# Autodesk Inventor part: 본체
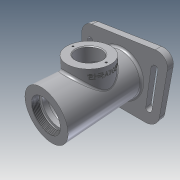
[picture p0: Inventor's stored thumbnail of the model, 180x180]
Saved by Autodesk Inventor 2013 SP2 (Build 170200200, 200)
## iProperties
Created: 2021-07
Part Number: 본체
Material: 알루미늄 6061
Document SubType Name: Modeling
Designer: kumcom17
Density: 2.71 g/cm^3
Mass: 738.12 g
Surface Area: 645.231 cm^2
Volume: 272.369 cm^3
Author: kumcom17
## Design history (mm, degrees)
sketch "스케치1"
  geometry: L1 (-56, 0)-(59, 0); L2 (59, 0)-(59, 31); L3 (59, 31)-(-56, 31); L4 (-56, 31)-(-56, 0); L5 (-56, 21)-(-47, 21); L6 (-47, 21)-(-47, 24); L7 (-47, 24)-(-44, 24); L8 (-44, 24)-(-44, 20); L9 (-44, 20)-(-37.5, 20); L10 (-35, 17.5)-(-35, 17.5); L11 (-35, 17.5)-(-31.75, 17.5); L12 (-31.75, 17.5)-(-31.75, 18.5); L13 (-31.75, 18.5)-(-30, 18.5); L14 (-30, 18.5)-(-30, 17.5); L15 (-30, 17.5)-(-19, 17.5); L16 (-19, 17.5)-(-19, 23); L17 (-16, 26)-(16, 26); L18 (19, 23)-(19, 17.5); L19 (19, 17.5)-(30, 17.5); L20 (30, 17.5)-(30, 16); L21 (30, 16)-(32, 16); L22 (35, 13)-(35, 10); L23 (35, 10)-(37.7, 10); L24 (37.7, 10)-(37.7, 12.5); L25 (37.7, 12.5)-(44.3, 12.5); L26 (44.3, 12.5)-(45, 12.904); L27 (45, 12.904)-(45, 14.022); L28 (46.818, 16.779)-(59, 22); A1 r 3 centre (-16, 23) between (-16, 26) and (-19, 23); A2 r 3 centre (16, 23) between (19, 23) and (16, 26); A3 r 3 centre (32, 13) between (35, 13) and (32, 16); A4 r 3 centre (48, 14.022) between (46.818, 16.779) and (45, 14.022); A5 r 2.5 centre (-37.5, 17.5) between (-35, 17.5) and (-37.5, 20); 4 further points
  constraints: 56 end point, 13 parallel, 12 perpendicular, 10 point on circle, 10 tangent, 9 point on line, 5 centre point, 3 equal radius, 1 horizontal
  dimensions: "d0" = 115 distance of L3.end L2.end; "d1" = 31 distance of L2.end L1.end; "d2" = 56 distance from line of point (0, 0) L4; "d3" = 42 diameter of L5 L1; "d4" = 48 diameter of L7 L1; "d5" = 40 diameter of L9 L1; "d6" = 35 diameter of L11 L1; "d7" = 35 diameter of L15 L1; "d8" = 37 diameter of L13 L1; "d9" = 52 diameter of L17 L1; "d10" = 35 diameter of L19 L1; "d11" = 30 deg angle of L26 L25; "d12" = 32 diameter of point (45, 16) L1; "d13" = 25 diameter of L25 L1; "d14" = 44 diameter of L28.end L1; "d15" = 14 distance between parallel lines of L2 L27; "d16" = 0.7 horizontal distance of L25.end L26.end; "d17" = 7.3 distance between parallel lines of L24 L27; "d18" = 24 distance between parallel lines of L2 L22; "d19" = 20 diameter of L23 L1; "d20" = 32 diameter of L21 L1; "d21" = 21 distance between parallel lines of L10 L4; "d22" = 12 distance between parallel lines of L8 L4; "d23" = 3 distance between parallel lines of L8 L6; "d24" = 65 distance between parallel lines of L20 L10; "d25" = 11 distance of L18.end L19.end; "d26" = 38 distance of point (-19, 26) point (19, 26); "d27" = 11 distance of L14.end L15.end; "d28" = 1.75 distance of L12.end L13.end; "d29" = 3 radius of A1; "d30" = 2.5 radius of A5
revolve "회전1" sketch "스케치1" stored, may be unused: angle "d31" = 90 deg
chamfer "모따기1" distance "d32" = 1; stored, may be unused: second distance "d33" = 2, angle "d34" = 45 deg
sketch "스케치2"
  geometry: C1 r 31 at (0, 0) reference; C2 r 35 at (0, 0)
  constraints: 1 centre point, 1 coincident
  dimensions: "d35" = 70 diameter of C2
extrude "돌출1" join sketch "스케치2" distance "d36" = 3; taper "d37" = 0 deg
sketch "스케치3"
  geometry: L1 (-42, 45)-(42, 45); L2 (58, 29)-(58, -29); L3 (42, -45)-(-42, -45); L4 (-58, -29)-(-58, 29); L5 (-58, 45)-(58, -45); L6 (58, 45)-(-58, -45); C1 r 31 at (0, 0) reference; C2 r 35 at (0, 0) reference; A1 r 16 centre (-42, 29) between (-42, 45) and (-58, 29); A2 r 16 centre (-42, -29) between (-58, -29) and (-42, -45); A3 r 16 centre (42, -29) between (42, -45) and (58, -29); A4 r 16 centre (42, 29) between (58, 29) and (42, 45)
  constraints: 12 end point, 8 point on circle, 8 point on line, 8 tangent, 4 centre point, 3 equal radius, 2 midpoint, 2 parallel, 1 horizontal, 1 perpendicular
  dimensions: "d38" = 116 distance of L5.end L6.end; "d39" = 90 distance of L6.start L5.end; "d40" = 16 radius of A1
extrude "돌출2" join sketch "스케치3" distance "d41" = 10; taper "d42" = 0 deg
sketch "스케치4"
  geometry: L1 (40, 25)-(48, 25); L2 (48, 25)-(48, -25); L3 (48, -25)-(40, -25); L4 (40, -25)-(40, 25); L5 (40, 25)-(48, -25); L6 (48, 25)-(40, -25); C1 r 35 at (0, 0) reference; 4 further points
  constraints: 12 end point, 5 midpoint, 3 horizontal alignment, 2 parallel, 1 horizontal, 1 perpendicular, 4 other
  dimensions: "d43" = 8 distance of L2.end L3.end; "d44" = 50 distance of L1.end L2.end; "d45" = 44 distance of point (44, 0) C1.centre
extrude "돌출3" cut sketch "스케치4" stored distance "d46" = 10; taper "d47" = 0 deg
fillet "모깎기1" dims "d48" = 0.3
node "작업 평면1"
sketch "스케치5"
  geometry: C1 r 27 at (0, 0); 1 further point
  constraints: 1 centre point, 1 coincident
  dimensions: "d50" = 54 diameter of C1
extrude "돌출4" join sketch "스케치5" stored distance "d51" = 10; taper "d52" = 0 deg
sketch "스케치6"
  geometry: C1 r 27 at (0, 0) reference; C2 r 16 at (0, 0)
  constraints: 1 centre point, 1 coincident
  dimensions: "d53" = 32 diameter of C2
extrude "돌출5" cut sketch "스케치6" stored distance "d54" = 10; taper "d55" = 0 deg
chamfer "모따기2" distance "d56" = 1; stored, may be unused: second distance "d57" = 2, angle "d58" = 45 deg
fillet "모깎기2" dims "d59" = 3
sketch "스케치7"
  geometry: C1 r 27 at (0, 0) reference; 1 further point
  constraints: 1 vertical alignment
  dimensions: "d60" = 22 distance of C1.centre point (0, 22)
hole "구멍1" sketch "스케치7" at (0, 22) diameter "d61" = 2.459; stored, may be unused: countersink angle "d65" = 90 deg, drill point angle "d67" = 118 deg; dims "d62" = 6, "d63" = 4, "d64" = 2, "d66" = 8
node "작업 평면2"
sketch "스케치8"
  geometry: L1 (-27, 42)-(27, 42) reference; 2 further points
  constraints: 1 vertical alignment, 1 other
  dimensions: "d69" = 8 distance from line of point (0, 34) L1
feature "엠보싱1" sketch "스케치8" dims "d70" = 0.5, "d71" = 0
fillet "모깎기3" dims "d72" = 3
feature "스레드1" dims "d73" = 10, "d74" = 0
node "솔리드1"
mirror "대칭1"
mirror "대칭2"
other parameters: "d49" = 42
